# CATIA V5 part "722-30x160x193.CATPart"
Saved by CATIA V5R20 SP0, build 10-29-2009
Part number: 722-30x160x193
Definition: NONE
Nomenclature: 722-30x160x193
Source: Unknown
Description: 722-30x160x193
Bounding box of the stored display mesh (mm): x -15 to 15, y -15 to 15, z -145 to 48
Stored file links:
  C:\Users\Utente\Desktop\IO LAVORO\3D X SITO CF\X SITO\722\722-30x160x193.CATPart
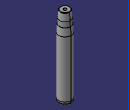
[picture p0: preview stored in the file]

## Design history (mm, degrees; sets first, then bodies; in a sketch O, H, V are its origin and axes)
Body1 "722-30x160x193" (main body)
  Solid1: solid without history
